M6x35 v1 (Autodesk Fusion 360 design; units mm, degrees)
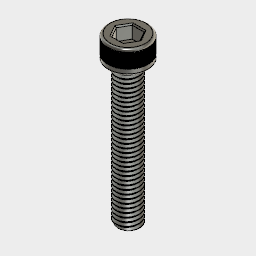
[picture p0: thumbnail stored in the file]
sketch "スケッチ1"
  circle C1 centre (0, 0) radius 3
  circle C2 centre (0, 0) radius 5
  dimension "d1" diameter C1 = 6
  dimension "d2" diameter C2 = 10
extrude "押し出し1" new body sketch "スケッチ1" blind 5.8
sketch "スケッチ2" plane through (0, 0, 5.8) normal (0, 0, 1) x axis (-1, 0, 0)
  line L1 (-1.4722, -2.55) -> (-2.9445, 0)
  line L2 (1.4722, -2.55) -> (-1.4722, -2.55)
  line L3 (2.9445, 0) -> (1.4722, -2.55)
  line L4 (1.4722, 2.55) -> (2.9445, 0)
  line L5 (-1.4722, 2.55) -> (1.4722, 2.55)
  line L6 (-2.9445, 0) -> (-1.4722, 2.55)
  circle C1 centre (0, 0) radius 5
  dimension "d5" distance L2 L5 = 5.1
work_plane "作業平面" sketch "スケッチ2" AlongDistance -0.75
extrude "押し出し2" cut sketch "スケッチ2" profile of L1 L2 L3 L4 L5 L6 against normal blind 3.3
chamfer "面取り" distance 0.3
sketch "スケッチ3" plane through (0, 0, 5.05) normal (0, 0, 1) x axis (1, 0, 0)
  line L1 (-0.05, 4.9497) -> (-0.05, 4.9997)
  line L2 (0.05, 4.9497) -> (-0.05, 4.9497)
  line L3 (0.05, 4.9997) -> (0.05, 4.9497)
  circle C1 centre (0, 0) radius 5
  point P4 (-0.05, 4.9497)
  point P5 (0.05, 4.9497)
  point P3 (-0.05, 4.9997)
  point P6 (0.05, 4.9997)
  dimension "d18" distance P4 P5 = 0.1
  dimension "d19" distance P3 P4 = 0.05
  dimension "d20" distance P5 P6 = 0.05 (= "d19")
extrude "押し出し3" cut sketch "スケッチ3" against normal blind 3.6
work_axis "作業軸"
circular_pattern "C パターン" countU 100 TotalAngle 360
fillet "フィレット1" radius 0.6
extrude "押し出し4" add sketch "スケッチ1" profile of C1 blind -35
thread "ねじ"
fillet "フィレット2" sketch "スケッチ3" radius 0.5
